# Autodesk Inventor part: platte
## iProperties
Shininess: 64.0
Length Units: 11269
Angle Units: 11279
Time Units: 11290
Mass Units: 11283
Length Display Precision: 3
Angle Display Precision: 2
Compacted: True
Part Number: platte
Document SubType Name: Modeling
Created: 2003-02
Material: Standard
Designer: Katja / W. Holzwarth
Density: 0.0
Volumn: 0.0
Area: 0.0
PropertySet Name: Model Information
Control State: 0
Master: False
Checked Out: False
Author: Katja / W.Holzwarth
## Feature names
1. Extrusion1
2. Extrusion2
